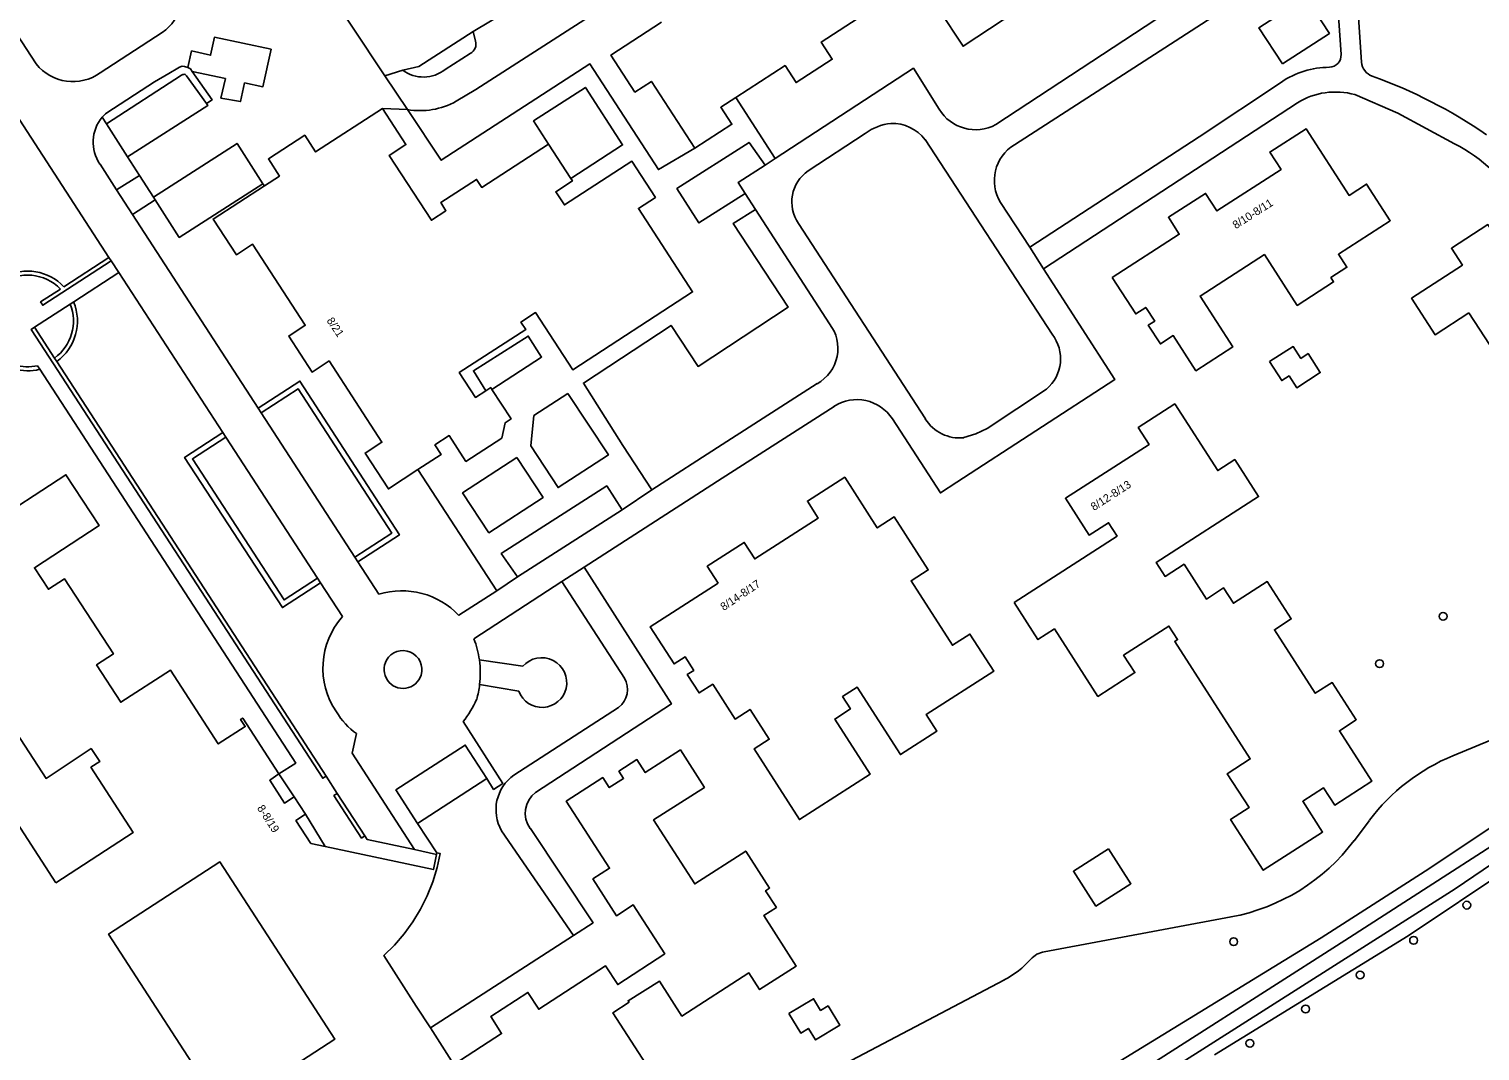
# Model space of a CAD drawing. Extents: x 159451 to 160663, y 388402 to 389723.
# Drawn here: x 159913.3 to 160094.7, y 389101.8 to 389229.6 of the extents above; entities that cross this region are included whole.
import ezdxf

# ---------------------------------------------------------------- set-up
doc = ezdxf.new("R2010")
doc.units = 0
for name, color, linetype in [('IMGEO_Boom', 7, 'Continuous'), ('IMGEO_Grasland_overig', 7, 'Continuous'), ('IMGEO_Groenvoorziening', 7, 'Continuous'), ('IMGEO_Haag', 7, 'Continuous'), ('IMGEO_Loofbos', 7, 'Continuous'), ('IMGEO_Pand', 7, 'Continuous'), ('IMGEO_Pand_nummerreeks', 7, 'Continuous'), ('IMGEO_Pand_overbouw', 7, 'Continuous'), ('IMGEO_Parkeervlak_gesloten', 7, 'Continuous'), ('IMGEO_Parkeervlak_open', 7, 'Continuous'), ('IMGEO_Rijbaan_lokaal_gesloten', 7, 'Continuous'), ('IMGEO_Rijbaan_lokaal_open', 7, 'Continuous'), ('IMGEO_Voetpad_gesloten', 7, 'Continuous'), ('IMGEO_Voetpad_open', 7, 'Continuous'), ('IMGEO_Waterloop', 7, 'Continuous')]:
    doc.layers.add(name, color=color, linetype=linetype)

msp = doc.modelspace()

# ---------------------------------------------------------------- linework, layer by layer
at = {"layer": 'IMGEO_Boom'}
for centre in [(160090.09, 389156.17), (160082.15, 389150.26), (160093.05, 389120.08), (160086.4, 389115.68), (160063.92, 389115.51), (160079.72, 389111.35), (160072.9, 389107.09), (160065.94, 389102.81)]:
    msp.add_circle(centre, 0.489, dxfattribs=at)
at = {"layer": 'IMGEO_Grasland_overig'}
msp.add_lwpolyline([(160153.98, 389168.11), (160132.54, 389150.12), (160127.01, 389145.62), (160098.42, 389124.73), (160085.71, 389116.26), (160061.52, 389101.37)], dxfattribs=at)
at = {"layer": 'IMGEO_Groenvoorziening'}
for points in [[(160070.01, 389225.22), (160075.89, 389229.04), (160072.95, 389233.56), (160067.07, 389229.74), (160070.01, 389225.22)], [(159922.5, 389218.55), (159923.02, 389217.75)], [(159963.52, 389104.72), (159981.42, 389116.3)]]:
    msp.add_lwpolyline(points, dxfattribs=at)
at = {"layer": 'IMGEO_Haag'}
for points in [[(159923.34, 389201.02), (159917.7, 389197.36)], [(159916.54, 389188.45), (159914.04, 389192.3)], [(159916.81, 389188.03), (159916.54, 389188.45)], [(159916.81, 389188.03), (159950.47, 389136.21)], [(159954.45, 389162.99), (159959.65, 389166.36), (159947.2, 389185.57), (159942, 389182.2)], [(159949.79, 389160.37), (159945.01, 389157.26), (159932.8, 389176.04), (159937.57, 389179.15)], [(159951.88, 389134.03), (159955.33, 389128.72)]]:
    msp.add_lwpolyline(points, dxfattribs=at)
for radius, start, end in [(6.23, 43.3041, 117.7763), (5.73, 306.0016, 21.5831), (6.23, 305.7753, 22.5008), (6.23, 223.4934, 284.2887)]:
    msp.add_arc((159913.17, 389193.09), radius, start, end, dxfattribs=at)
at = {"layer": 'IMGEO_Loofbos'}
for points in [[(160103.46, 389143.76), (160091.31, 389138.74)], [(160080.89, 389130.67), (160078.97, 389128.13)], [(160045.8, 389098.21), (160074.84, 389116.01), (160087.85, 389124.34), (160097.16, 389130.51)], [(160063.58, 389118.6), (160040.24, 389114.26)], [(160035.25, 389110.74), (160011.36, 389098.17)]]:
    msp.add_lwpolyline(points, dxfattribs=at)
for centre, radius, start, end in [((160100.86, 389115.63), 25.01, 112.4624, 143.0084), ((160059, 389143.18), 25, 280.5385, 323.0102), ((160029.67, 389121.34), 11.98, 297.7353, 317.9357), ((160040.79, 389111.31), 3, 100.5123, 137.95)]:
    msp.add_arc(centre, radius, start, end, dxfattribs=at)
at = {"layer": 'IMGEO_Pand'}
for points in [[(160020.79, 389233.42), (160012.36, 389227.95), (160013.75, 389225.81), (160009.22, 389222.88), (160007.84, 389225.01), (160001.7, 389221.03)], [(160038.4, 389232.89), (160030.09, 389227.43), (160027.07, 389232.03)], [(159996.56, 389214.67), (159991.13, 389223.04), (159989.07, 389221.71), (159986.07, 389226.32), (159992.41, 389230.43)], [(159942.76, 389209.97), (159944.65, 389211.2), (159943.26, 389213.35), (159947.82, 389216.31), (159949.17, 389214.22), (159957.53, 389219.64)], [(159957.53, 389219.64), (159960.45, 389215.13), (159958.38, 389213.79), (159963.64, 389205.69), (159965.46, 389206.86), (159964.8, 389207.88), (159969.29, 389210.79), (159969.94, 389209.79), (159978.29, 389215.21)], [(159996.56, 389214.67), (160001.19, 389217.67), (159999.81, 389219.8), (160001.7, 389221.03)], [(160048.73, 389198.53), (160057.12, 389203.94), (160055.76, 389206.05), (160060.4, 389209.04), (160061.81, 389206.85), (160069.83, 389212.03), (160068.43, 389214.2), (160072.96, 389217.11), (160078.33, 389208.78), (160080.53, 389210.2), (160083.49, 389205.61), (160077.01, 389201.43), (160078.06, 389199.8), (160076.06, 389198.51), (160076.41, 389197.97), (160071.85, 389195.03), (160067.75, 389201.39), (160059.71, 389196.2), (160063.8, 389189.85), (160059.19, 389186.88), (160056.36, 389191.27), (160054.75, 389190.22), (160053.24, 389192.56), (160054.04, 389193.08), (160052.93, 389194.79), (160051.67, 389193.98), (160048.73, 389198.53)], [(159978.29, 389215.21), (159981.08, 389210.9)], [(159981.08, 389210.9), (159981.27, 389210.6), (159979.19, 389209.25), (159980.27, 389207.59), (159988.7, 389213.06), (159991.63, 389208.54), (159989.51, 389207.16), (159996.29, 389196.72), (159981.31, 389186.99), (159976.66, 389194.15), (159974.82, 389192.95), (159975.43, 389192.02), (159967.13, 389186.64), (159969.15, 389183.53), (159970.46, 389184.38)], [(159942.76, 389209.97), (159936.36, 389205.82), (159939.26, 389201.36), (159941.29, 389202.68), (159947.88, 389192.55), (159945.81, 389191.21), (159948.73, 389186.71), (159950.85, 389188.09), (159957.45, 389177.93), (159955.36, 389176.58), (159958.27, 389172.11), (159961.96, 389174.51)], [(160093.32, 389194.12), (160089.09, 389191.36), (160086.16, 389195.94), (160092.5, 389200.07), (160091.12, 389202.18), (160095.66, 389205.14), (160101.13, 389196.74), (160103.22, 389198.1), (160106.21, 389193.51), (160104.05, 389192.1), (160109.28, 389184.09), (160111.35, 389185.44), (160114.25, 389181.01), (160105.82, 389175.51), (160107.18, 389173.42), (160102.63, 389170.46), (160096.94, 389179.18), (160101.23, 389181.98), (160093.32, 389194.12)], [(160068.4, 389188.01), (160071.36, 389189.9), (160072.31, 389188.42), (160073.22, 389189.01), (160074.74, 389186.65), (160071.79, 389184.75), (160070.84, 389186.23), (160069.92, 389185.64), (160068.4, 389188.01)], [(159971.21, 389184.53), (159973.6, 389180.85), (159972.87, 389180.38), (159972.46, 389178.46), (159967.96, 389175.54), (159965.87, 389178.76), (159964.08, 389177.6), (159964.86, 389176.4), (159961.96, 389174.51)], [(159970.46, 389184.38), (159971.06, 389184.77), (159971.21, 389184.53)], [(160036.46, 389157.9), (160049.34, 389166.2), (160048.27, 389167.87), (160045.85, 389166.32), (160042.88, 389170.93), (160053.34, 389177.67), (160051.98, 389179.77), (160056.55, 389182.72), (160061.92, 389174.39), (160064.05, 389175.76), (160067.02, 389171.15), (160054.21, 389162.9), (160055.34, 389161.16), (160057.71, 389162.69), (160060.51, 389158.34), (160062.66, 389159.72), (160063.89, 389157.8), (160068.11, 389160.51), (160071.11, 389155.85), (160069.01, 389154.49), (160074.12, 389146.55), (160076.23, 389147.9), (160079.23, 389143.24), (160077.13, 389141.88), (160081.19, 389135.58), (160076.54, 389132.58), (160075.16, 389134.73), (160072.55, 389133.06), (160075.03, 389129.21), (160067.62, 389124.43), (160063.53, 389130.79), (160065.84, 389132.28), (160063.12, 389136.5), (160065.99, 389138.35), (160056.55, 389153.03), (160056.91, 389153.26), (160055.82, 389154.95), (160050.16, 389151.31), (160051.56, 389149.14), (160046.95, 389146.17), (160041.51, 389154.6), (160039.44, 389153.27), (160036.46, 389157.9)], [(159883.95, 389168.97), (159894.08, 389175.55), (159894.44, 389175), (159897.74, 389177.11), (159901.34, 389176.34), (159903.49, 389173.04), (159904.05, 389173.41), (159907.94, 389167.36), (159917.95, 389173.87), (159922.1, 389167.52), (159914.03, 389162.25), (159915.78, 389159.56), (159917.79, 389160.86), (159923.89, 389151.47), (159921.79, 389150.11), (159924.82, 389145.44), (159931.02, 389149.46), (159937, 389140.22), (159940.37, 389142.4), (159939.8, 389143.29), (159940.07, 389143.45), (159944.59, 389136.47)], [(159999.48, 389160.31), (159998.11, 389162.44), (160002.75, 389165.41), (160004.06, 389163.36), (160012, 389168.46), (160010.64, 389170.57), (160015.3, 389173.55), (160019.36, 389167.23), (160021.49, 389168.59), (160025.73, 389161.98), (160023.6, 389160.62), (160028.77, 389152.55), (160030.95, 389153.95), (160033.92, 389149.32), (160025.49, 389143.91), (160026.82, 389141.83), (160022.27, 389138.9), (160016.87, 389147.32), (160015.03, 389146.14), (160016.02, 389144.6), (160014.05, 389143.34), (160018.47, 389136.44), (160009.63, 389130.77), (160003.97, 389139.6), (160005.86, 389140.82), (160003.48, 389144.54), (160001.6, 389143.33), (159998.8, 389147.69), (159997.1, 389146.6), (159995.62, 389148.9), (159996.44, 389149.42), (159995.36, 389151.1), (159993.98, 389150.22), (159991, 389154.87), (159999.48, 389160.31)], [(159916.68, 389122.87), (159908.73, 389135.13), (159900.67, 389129.9), (159896.4, 389136.48), (159900.41, 389139.07), (159893.57, 389149.61), (159891.55, 389148.29), (159887.76, 389154.14), (159901.31, 389162.64), (159902.96, 389160.02), (159900.68, 389158.6), (159915.48, 389135.92), (159921.11, 389139.65), (159922.18, 389138.02), (159921.08, 389137.31), (159926.37, 389129.16), (159916.68, 389122.87)], [(159963.52, 389104.72), (159966.44, 389100.16), (159972.42, 389104.03), (159971.05, 389106.14), (159975.71, 389109.16), (159977.06, 389107.07), (159985.42, 389112.47), (159986.93, 389110.15), (159992.8, 389113.99), (159988.87, 389120.11), (159986.77, 389118.76), (159983.82, 389123.35), (159985.9, 389124.68), (159980.5, 389133.07), (159985.06, 389136.01), (159985.86, 389134.76), (159987.65, 389135.91), (159987.08, 389136.81), (159989.33, 389138.27), (159990.37, 389136.65), (159994.76, 389139.48), (159997.77, 389134.8), (159991.42, 389130.72), (159996.56, 389122.73), (160002.93, 389126.83), (160005.91, 389122.2), (160005.41, 389121.88), (160006.76, 389119.8), (160005.18, 389118.78), (160009.24, 389112.46), (160004.66, 389109.52), (160003.33, 389111.6), (159994.96, 389106.21), (159992.14, 389110.59), (159988.23, 389108.13), (159988.35, 389107.95), (159986.32, 389106.63), (159990.44, 389100.26)], [(159944.59, 389136.47), (159943.44, 389135.68), (159945.27, 389132.84), (159946.48, 389133.63), (159947.9, 389131.43), (159946.7, 389130.65), (159948.58, 389127.79), (159950.37, 389127.41), (159963.89, 389124.52), (159964.29, 389126.42)], [(160048.26, 389127.13), (160051.07, 389122.76), (160046.7, 389119.95), (160043.89, 389124.32), (160048.26, 389127.13)], [(159937.66, 389094.3), (159923.3, 389116.46), (159937.2, 389125.47), (159951.56, 389103.31), (159937.66, 389094.3)], [(159964.33, 389126.63), (159964.73, 389126.55), (159964.35, 389124.76), (159963.81, 389122.98), (159963.12, 389121.25), (159962.29, 389119.57), (159961.32, 389117.97), (159960.22, 389116.47), (159959.01, 389115.07), (159957.7, 389113.79), (159961.75, 389107.46), (159963.52, 389104.72)], [(159964.29, 389126.42), (159964.33, 389126.63)], [(160008.33, 389106.52), (160009.81, 389104.09), (160010.77, 389104.67), (160011.65, 389103.23), (160014.68, 389105.06), (160013.21, 389107.48), (160012.29, 389106.91), (160011.4, 389108.38), (160008.33, 389106.52)]]:
    msp.add_lwpolyline(points, dxfattribs=at)
at = {"layer": 'IMGEO_Pand_overbouw'}
for points in [[(159946.48, 389133.63), (159944.59, 389136.47), (159943.44, 389135.68), (159945.27, 389132.84)], [(159950.37, 389127.41), (159947.9, 389131.43), (159946.7, 389130.65), (159948.58, 389127.79)]]:
    msp.add_lwpolyline(points, close=True, dxfattribs=at)
at = {"layer": 'IMGEO_Parkeervlak_gesloten'}
for points in [[(159935.55, 389220.26), (159933.04, 389223.75), (159932.96, 389223.83), (159932.88, 389223.89), (159932.8, 389223.92), (159932.66, 389223.91), (159932.59, 389223.89), (159932.49, 389223.86), (159932.41, 389223.83), (159923.02, 389217.75)], [(159923.02, 389217.75), (159925.67, 389213.61)], [(159954.07, 389163.57), (159958.69, 389166.57), (159946.99, 389184.6), (159942.38, 389181.61)], [(159937.96, 389178.56), (159933.76, 389175.84), (159945.22, 389158.23), (159949.41, 389160.96)]]:
    msp.add_lwpolyline(points, dxfattribs=at)
at = {"layer": 'IMGEO_Parkeervlak_open'}
for points in [[(159960.05, 389224.43), (159962.06, 389224.9), (159968.86, 389229.29)], [(159933.21, 389224.77), (159933.54, 389224.59), (159933.73, 389224.28)], [(159929.12, 389208.23), (159932.13, 389203.53), (159942.59, 389210.24)], [(159970.58, 389135.89), (159961.91, 389130.28)]]:
    msp.add_lwpolyline(points, dxfattribs=at)
at = {"layer": 'IMGEO_Rijbaan_lokaal_gesloten'}
for points in [[(159966.74, 389220.55), (159969.19, 389222.03), (160041.99, 389268.82)], [(159973, 389231.74), (159968.86, 389229.29)], [(159968.86, 389229.29), (159969.16, 389228.08)], [(159968.5, 389226.54), (159965.37, 389224.54)], [(159960.05, 389224.43), (159957.82, 389223.75)], [(159960.64, 389219.52), (159957.82, 389223.75)]]:
    msp.add_lwpolyline(points, dxfattribs=at)
for centre, radius, start, end in [((159967.93, 389227.69), 1.28, 296.3961, 17.2519), ((159962.64, 389227.95), 4.37, 233.6418, 308.6854), ((159962.24, 389228.59), 9.21, 259.9816, 299.2142)]:
    msp.add_arc(centre, radius, start, end, dxfattribs=at)
at = {"layer": 'IMGEO_Rijbaan_lokaal_open'}
for points in [[(160072.99, 389243.15), (160034.2, 389217.64)], [(160036.5, 389215.12), (160068.36, 389235.7), (160076.35, 389240.87)], [(159914.25, 389225.23), (159906.39, 389237.24)], [(159957.82, 389223.75), (159949.55, 389236.19)], [(159930, 389229.16), (159922.25, 389224.11)], [(159933.21, 389224.77), (159933.66, 389226.85), (159936.04, 389226.3), (159936.52, 389228.55), (159943.6, 389227.05), (159942.58, 389222.36), (159940.3, 389222.84), (159939.76, 389220.51), (159937.34, 389220.96), (159937.9, 389223.38), (159933.73, 389224.28)], [(159906.77, 389226.48), (159923.34, 389201.02)], [(159923.06, 389219.11), (159929.01, 389222.99), (159930.82, 389224.04), (159931.93, 389224.69), (159932.16, 389224.82), (159932.48, 389224.94), (159932.8, 389224.9), (159933.21, 389224.77)], [(159933.73, 389224.28), (159936.23, 389220.72), (159935.55, 389220.26)], [(160027.09, 389219.58), (160023.88, 389224.68), (160006.59, 389213.4)], [(159935.55, 389220.26), (159935.71, 389220.04), (159925.67, 389213.61)], [(159957.53, 389219.64), (159960.64, 389219.52)], [(160010.74, 389211.86), (160017.84, 389216.54)], [(159928.89, 389208.58), (159939.35, 389215.29), (159942.59, 389210.24)], [(160025.35, 389215.76), (160041.22, 389191.43)], [(159924.29, 389209.5), (159922.23, 389212.7)], [(159925.67, 389213.61), (159927.16, 389211.29)], [(160005.34, 389212.58), (160001.98, 389210.39), (160002.85, 389209.04)], [(160006.59, 389213.4), (160005.34, 389212.58)], [(159924.29, 389209.5), (159927.16, 389211.29)], [(159927.16, 389211.29), (159928.89, 389208.58)], [(159926.29, 389206.42), (159924.29, 389209.5)], [(159942.59, 389210.24), (159942.76, 389209.97)], [(160002.85, 389209.04), (160004.14, 389207.04)], [(159926.29, 389206.42), (159929.12, 389208.23)], [(159929.12, 389208.23), (159928.89, 389208.58)], [(160004.14, 389207.04), (160013.39, 389192.75)], [(160038.43, 389202.32), (160034.78, 389207.9)], [(159942, 389182.2), (159926.29, 389206.42)], [(160025.38, 389180.86), (160009.52, 389205.29)], [(160038.43, 389202.32), (160040.16, 389199.62)], [(159923.34, 389201.02), (159923.61, 389200.6)], [(159923.61, 389200.6), (159924.57, 389199.14)], [(160021.26, 389180.85), (160027.27, 389171.6), (160029.31, 389172.93), (160049.04, 389185.76), (160040.16, 389199.62)], [(159924.57, 389199.14), (159937.57, 389179.15)], [(160011.84, 389185.26), (160000, 389177.64), (159991.19, 389171.98)], [(160040.51, 389184.57), (160033.09, 389179.66), (160031.69, 389178.97), (160030.2, 389178.51)], [(159942.38, 389181.61), (159942, 389182.2)], [(159954.07, 389163.57), (159942.38, 389181.61)], [(159982.74, 389162.32), (160000, 389173.44), (160013.96, 389182.42)], [(159937.57, 389179.15), (159937.96, 389178.56)], [(159937.96, 389178.56), (159949.41, 389160.96)], [(159991.19, 389171.98), (159987.48, 389169.5)], [(159987.48, 389169.5), (159974.39, 389161.13)], [(159954.45, 389162.99), (159954.07, 389163.57)], [(159957.06, 389158.96), (159954.45, 389162.99)], [(159979.95, 389160.51), (159982.74, 389162.32)], [(159949.41, 389160.96), (159949.79, 389160.37)], [(159949.79, 389160.37), (159952.53, 389156.15)], [(159968.95, 389153.36), (159979.95, 389160.51)], [(159974.39, 389161.13), (159971.81, 389159.35)], [(159971.81, 389159.35), (159967.08, 389156.3)], [(159954.29, 389141.51), (159953.74, 389139.06), (159961.53, 389127.02)], [(159970.58, 389135.89), (159971.42, 389134.54), (159972.56, 389135.28), (159967.6, 389143.02)], [(159961.91, 389130.28), (159959.2, 389134.48), (159967.86, 389140.08), (159970.58, 389135.89)], [(159964.33, 389126.63), (159961.91, 389130.28)], [(159961.53, 389127.02), (159964.29, 389126.42)]]:
    msp.add_lwpolyline(points, dxfattribs=at)
for centre, radius, start, end in [((159926.93, 389233.71), 5.49, 303.9825, 31.7375), ((159918.84, 389228.86), 5.85, 218.3532, 305.7233), ((160031.66, 389222.34), 5.34, 211.2132, 298.3789), ((159926.19, 389215.44), 4.83, 139.8899, 214.6509), ((159926.08, 389215.55), 4.67, 130.4209, 140.0939), ((160021.89, 389210.9), 6.94, 96.7893, 125.6448), ((160021.25, 389212.66), 5.13, 37.0681, 92.0302), ((160039.25, 389210.65), 5.25, 121.5919, 211.583), ((160013.43, 389207.96), 4.74, 124.6581, 214.4027), ((160009.42, 389189.66), 5.03, 298.8712, 37.8537), ((160037.32, 389188.37), 4.96, 309.9008, 38.181), ((160016.82, 389177.97), 5.29, 32.9971, 122.7747), ((160029.64, 389183.48), 5.01, 211.6208, 276.396), ((159959.91, 389149.48), 9.89, 43.552, 106.7454), ((159959.76, 389149.71), 9.68, 138.2961, 214.3823), ((159957.64, 389149.04), 12.11, 7.9949, 20.9234), ((159960.09, 389149.53), 2.37, 150.4782, 342.9011), ((159960.08, 389149.52), 2.37, 343.1217, 150.2575), ((159957.64, 389149.04), 12.11, 353.3656, 7.9741), ((159957.59, 389149.05), 12.16, 344.4296, 353.3315), ((159958.03, 389150.8), 12.33, 320.8729, 336.0275), ((159959.31, 389148.67), 8.74, 210.441, 234.976)]:
    msp.add_arc(centre, radius, start, end, dxfattribs=at)
at = {"layer": 'IMGEO_Voetpad_gesloten'}
for points in [[(160076.35, 389240.87), (160077.34, 389226.4)], [(160079.9, 389225.44), (160078.87, 389240.47)], [(160069.88, 389222.95), (160059.58, 389216.09), (160038.43, 389202.32)], [(160079.06, 389221.38), (160084.42, 389219.08), (160091.53, 389215.25)], [(160040.16, 389199.62), (160071.89, 389220.37)], [(159976.67, 389134.17), (159993.64, 389145.22), (159982.74, 389162.32)], [(159979.95, 389160.51), (159987.77, 389148.46)], [(159987.03, 389144.79), (159973.96, 389136.33)], [(159972.41, 389129.37), (159981.42, 389116.3)], [(159981.42, 389116.3), (159983.84, 389117.87), (159976.01, 389129.66)]]:
    msp.add_lwpolyline(points, dxfattribs=at)
for centre, radius, start, end in [((160075.84, 389226.3), 1.5, 271.3812, 3.8511), ((160081.9, 389225.58), 2, 183.9538, 249.8911), ((160075.84, 389214.25), 10.55, 89.8332, 124.4314), ((160059.62, 389163.99), 63.5, 55.5826, 70.1199), ((160076.64, 389212.6), 9.11, 74.6376, 121.4412), ((160081.39, 389195.93), 21.82, 31.964, 62.3071), ((159985.31, 389147.04), 2.84, 307.436, 29.9141), ((159977.01, 389131.99), 5.3, 125.1, 209.6489), ((159978.59, 389131.58), 3.22, 126.6873, 216.5787)]:
    msp.add_arc(centre, radius, start, end, dxfattribs=at)
at = {"layer": 'IMGEO_Voetpad_open'}
for points in [[(159960.64, 389219.52), (159964.87, 389213.17), (159983.45, 389225.22), (159992.01, 389212.02), (159996.56, 389214.67)], [(159978.29, 389215.21), (159976.42, 389218.09), (159982.88, 389222.28), (159987.54, 389215.1), (159981.08, 389210.9)], [(160001.7, 389221.03), (160006.59, 389213.4)], [(160005.34, 389212.58), (160003.34, 389215.4), (159994.33, 389209.63), (159997.08, 389205.34), (160002.85, 389209.04)], [(160004.14, 389207.04), (160001.35, 389205.26), (160008.23, 389194.81), (159996.97, 389187.41), (159993.6, 389192.53), (159982.65, 389185.33), (159987.56, 389177.52), (159991.19, 389171.98)], [(159917.28, 389197.08), (159914.79, 389195.47), (159915.07, 389195.05), (159923.61, 389200.6)], [(159918.93, 389195.47), (159924.57, 389199.14)], [(159914.04, 389192.3), (159918.5, 389195.2)], [(159918.5, 389195.2), (159918.93, 389195.47)], [(159950.47, 389136.21), (159950.05, 389135.94), (159913.62, 389192.03), (159914.04, 389192.3)], [(159971.21, 389184.53), (159977.42, 389188.57), (159975.75, 389191.2), (159968.9, 389186.86), (159970.46, 389184.38)], [(159914.42, 389187.49), (159914.71, 389187.05)], [(159914.71, 389187.05), (159946.68, 389137.83), (159944.59, 389136.47)], [(159980.71, 389184.04), (159976.46, 389181.27), (159976.05, 389177.48), (159979.48, 389172.27), (159985.77, 389176.35), (159980.71, 389184.04)], [(159974.31, 389176.02), (159967.54, 389171.61), (159970.82, 389166.63), (159977.59, 389171.04), (159974.31, 389176.02)], [(159961.96, 389174.51), (159971.81, 389159.35)], [(159974.39, 389161.13), (159972.36, 389164.01), (159985.55, 389172.48), (159987.48, 389169.5)], [(159969.63, 389150.72), (159975.05, 389149.93)], [(159974.57, 389146.81), (159969.67, 389147.64)], [(159951.88, 389134.03), (159950.47, 389136.21)], [(159955.33, 389128.72), (159954.91, 389128.45), (159951.46, 389133.76), (159951.88, 389134.03)], [(159961.53, 389127.02), (159955.62, 389128.28), (159955.33, 389128.72)]]:
    msp.add_lwpolyline(points, dxfattribs=at)
for centre, radius, start, end in [((159913.17, 389193.09), 5.73, 44.2159, 206.8512), ((159913.17, 389193.09), 5.73, 224.4279, 282.5875), ((159977.42, 389147.86), 3.14, 347.055, 138.8731), ((159977.47, 389147.88), 3.09, 200.2256, 346.5119)]:
    msp.add_arc(centre, radius, start, end, dxfattribs=at)
at = {"layer": 'IMGEO_Waterloop'}
for points in [[(160107.18, 389134.57), (160077.82, 389115.65), (160047.7, 389096.41)], [(160049.43, 389095.33), (160091.59, 389122.12), (160108.05, 389133.27)]]:
    msp.add_lwpolyline(points, dxfattribs=at)

# ---------------------------------------------------------------- texts
at = {"layer": 'IMGEO_Pand_nummerreeks'}
for s, rotation, p in [('8/10-8/11', 32.5124, (160064.18, 389204.55)), ('8/21', 303.747, (159950.5, 389193.13)), ('8/12-8/13', 32.8427, (160046.45, 389169.33)), ('8/14-8/17', 33.9538, (160000.18, 389156.83)), ('8-8/19', 302.812, (159941.81, 389132.21))]:
    msp.add_text(s, height=1, rotation=rotation, dxfattribs=at).set_placement(p)

doc.saveas('drawing.dxf')
